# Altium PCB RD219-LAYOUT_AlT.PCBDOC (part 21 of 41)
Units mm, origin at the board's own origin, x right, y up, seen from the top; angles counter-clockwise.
Board outline 209.75 x 159.97 mm, 2 copper layers (TOP, BOTTOM), stack 0 mm thick; 398 components, 199 nets, 1469 pads, 0 vias.
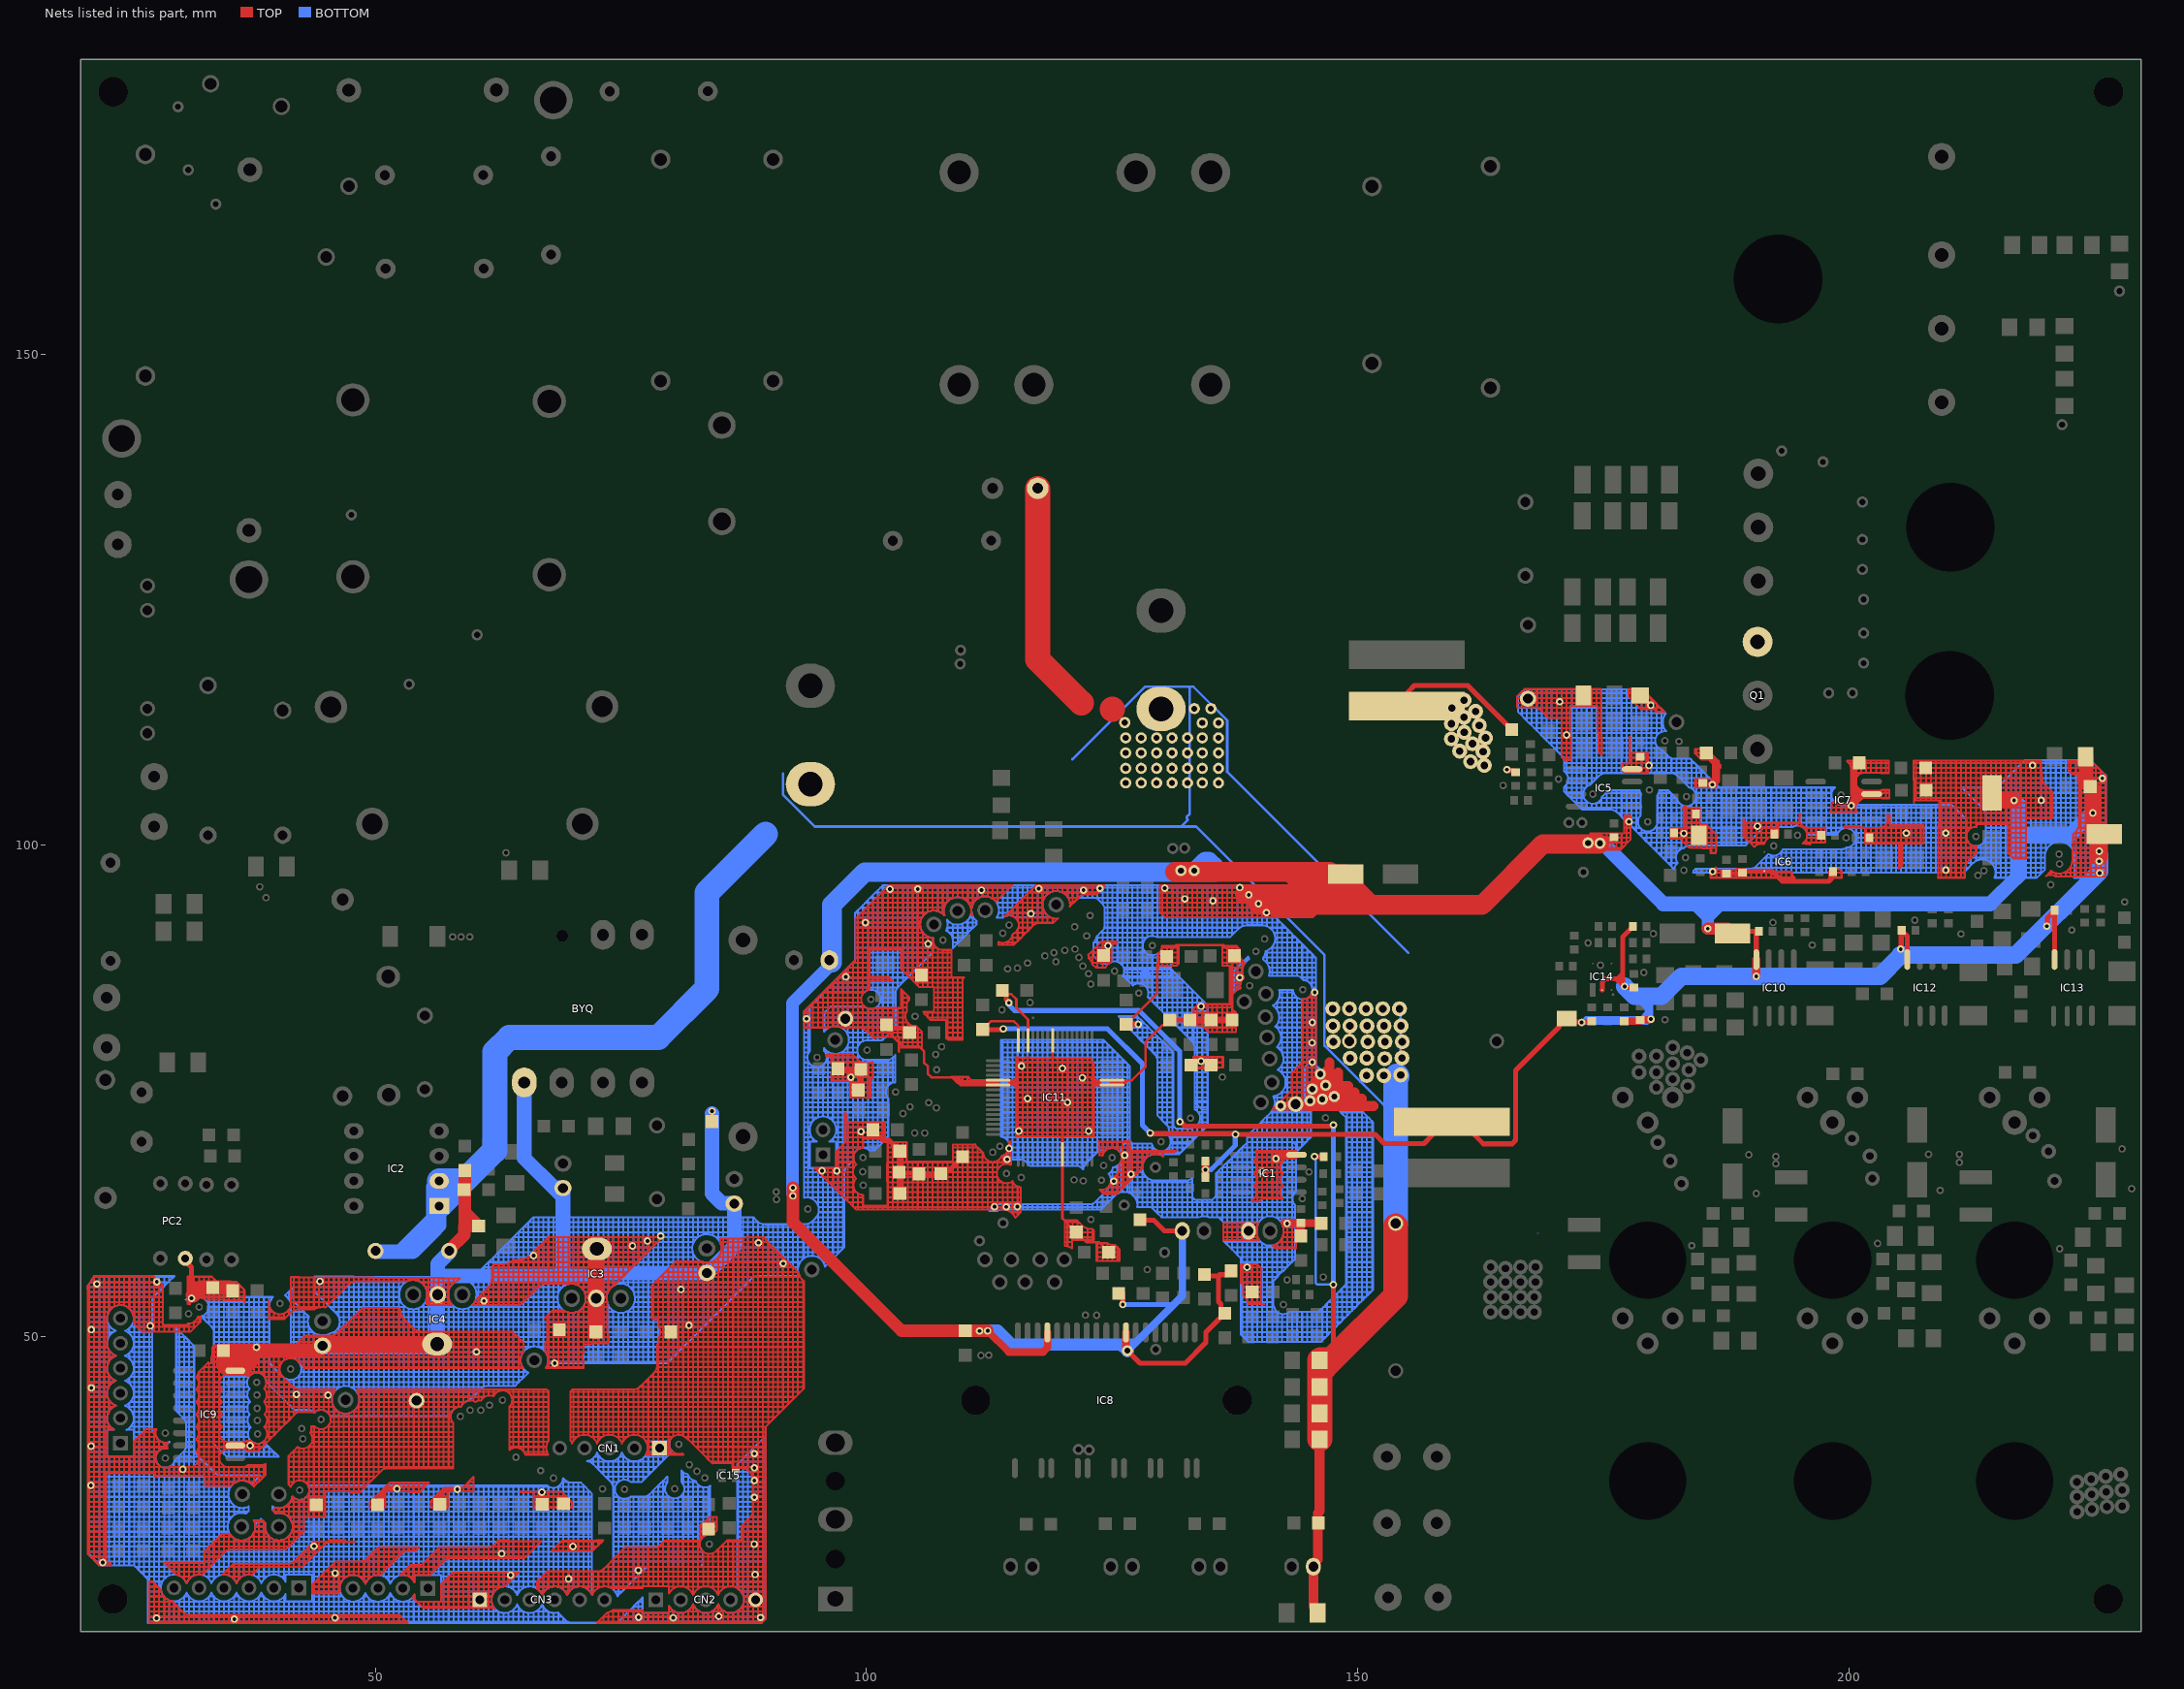
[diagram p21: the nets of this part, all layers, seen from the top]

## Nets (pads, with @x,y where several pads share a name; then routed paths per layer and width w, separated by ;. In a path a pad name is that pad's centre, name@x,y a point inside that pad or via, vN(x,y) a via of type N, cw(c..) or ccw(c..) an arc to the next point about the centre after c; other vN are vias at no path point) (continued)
GND: (continued)
  BOTTOM w0.203: 29.525,25.797 29.525,26.096 ; 29.525,26.096 29.525,26.604 ; 29.525,26.096 30.033,26.096 ; 29.525,26.604 30.033,26.604 ; 29.525,26.604 29.525,27.112 ; 29.525,27.112 29.525,27.62 ; 29.525,27.112 30.033,27.112 ; 29.525,27.62 29.525,28.128 ; 29.525,27.62 30.033,27.62 ; 29.525,28.128 29.525,28.636 ; 29.525,28.128 30.033,28.128 ; 29.525,28.636 29.525,29.144 ; 29.525,28.636 30.033,28.636 ; 29.525,29.144 29.525,29.652 ; 29.525,29.144 30.033,29.144 ; 29.525,29.652 29.525,30.16 ; 29.525,29.652 30.033,29.652 ; 29.525,30.16 29.525,30.668 ; 29.525,30.16 30.033,30.16 ; 29.525,30.668 29.525,31.176 ; 29.525,30.668 30.033,30.668 ; 29.525,31.176 29.525,31.684 ; 29.525,31.176 30.033,31.176 ; 29.525,31.684 29.525,32.192 ; 29.525,31.684 30.033,31.684 ; 29.525,32.192 29.525,32.7 ; 29.525,32.192 30.033,32.192 ; 29.525,32.7 29.525,33.208 ; 29.525,32.7 30.033,32.7 ; 29.525,33.208 29.525,33.716 ; 29.525,33.208 30.033,33.208 ; 29.525,33.716 29.525,34.224 ; 29.525,33.716 30.033,33.716 ; 29.525,34.224 29.525,34.732 ; 29.525,34.224 30.033,34.224 ; 29.525,34.732 29.525,35.24 ; 29.525,34.732 30.033,34.732 ; 29.525,35.24 29.525,35.748 ; 29.525,35.24 30.033,35.24 ; 29.525,35.748 29.525,36.256 ; 29.525,35.748 30.033,35.748 ; 29.525,36.256 30.033,36.256 ; 29.525,36.256 29.525,36.764 ; 29.525,36.764 30.033,36.764 ; 29.525,36.764 29.525,37.234 ; 29.525,37.234 ccw(c28.636,37.653) 29.542,37.272 ; 29.542,37.272 ccw(c28.636,37.653) 29.585,37.397 ; 29.542,37.272 30.033,37.272 ; 29.585,37.397 29.967,37.78 ; 29.742,42.86 30.033,42.86 ; 29.742,42.86 29.742,43.368 ; 29.742,42.86 29.742,42.451 29.84,42.352 ; 29.742,43.368 30.033,43.368 ; 29.742,43.368 29.742,43.876 ; 29.742,43.876 30.033,43.876 ; 29.742,43.876 29.742,44.384 ; 29.742,44.384 30.033,44.384 ; 29.742,44.384 29.742,44.892 ; 29.742,44.892 30.033,44.892 ; 29.742,44.892 29.742,45.4 ; 29.742,45.4 30.033,45.4 ; 29.742,45.4 29.742,45.908 ; 29.742,45.908 30.033,45.908 ; 29.742,45.908 29.742,46.416 ; 29.742,46.416 30.033,46.416 ; 29.742,46.416 29.742,46.924 ; 29.742,46.924 30.033,46.924 ; 29.742,46.924 29.742,47.432 ; 29.742,47.432 30.033,47.432 ; 29.742,47.432 29.742,47.94 ; 29.742,47.94 30.033,47.94 ; 29.742,47.94 29.742,48.448 ; 29.742,48.448 29.742,48.956 ; 29.742,48.448 30.033,48.448 ; 29.742,48.956 29.742,49.464 ; 29.742,48.956 30.033,48.956 ; 29.742,49.464 29.742,49.972 ; 29.742,49.464 30.033,49.464 ; 29.742,49.972 29.742,50.48 ; 29.742,49.972 30.033,49.972 ; 29.742,50.48 30.033,50.48 ; 29.742,50.48 29.742,50.884 30.033,50.593 ; 29.84,42.352 30.033,42.159 ; 29.84,42.352 30.033,42.352 ; 29.967,37.78 30.033,37.78 ; 29.967,37.78 30.033,37.846 ; 30.033,20.889 30.033,21.016 ; 30.033,20.889 30.541,20.889 ; 30.033,21.016 30.033,21.524 ; 30.033,21.016 30.541,21.016 ; 30.033,21.524 30.033,22.032 ; 30.033,21.524 30.541,21.524 ; 30.033,22.032 30.033,22.54 ; 30.033,22.032 30.541,22.032 ; 30.033,22.54 30.033,23.048 ; 30.033,22.54 30.541,22.54 ; 30.033,23.048 30.541,23.048 ; 30.033,23.048 30.033,23.192 ; 30.033,23.192 ccw(c29.525,24.445) 30.541,23.554 ; 30.033,25.698 30.033,26.096 ; 30.033,26.096 30.033,26.604 ; 30.033,26.096 30.541,26.096 ; 30.033,26.604 30.541,26.604 ; 30.033,26.604 30.033,27.112 ; 30.033,27.112 30.033,27.62 ; 30.033,27.112 30.541,27.112 ; 30.033,27.62 30.033,28.128 ; 30.033,27.62 30.541,27.62 ; 30.033,28.128 30.033,28.636 ; 30.033,28.128 30.541,28.128 ; 30.033,28.636 30.033,29.144 ; 30.033,28.636 30.541,28.636 ; 30.033,29.144 30.033,29.652 ; 30.033,29.144 30.541,29.144 ; 30.033,29.652 30.033,30.16 ; 30.033,29.652 30.541,29.652 ; 30.033,30.16 30.033,30.668 ; 30.033,30.16 30.541,30.16 ; 30.033,30.668 30.033,31.176 ; 30.033,30.668 30.541,30.668 ; 30.033,31.176 30.033,31.684 ; 30.033,31.176 30.541,31.176 ; 30.033,31.684 30.033,32.192 ; 30.033,31.684 30.541,31.684 ; 30.033,32.192 30.541,32.192 ; 30.033,32.192 30.033,32.7 ; 30.033,32.7 30.033,33.208 ; 30.033,32.7 30.541,32.7 ; 30.033,33.208 30.033,33.716 ; 30.033,33.208 30.541,33.208 ; 30.033,33.716 30.033,34.224 ; 30.033,33.716 30.541,33.716 ; 30.033,34.224 30.033,34.732 ; 30.033,34.224 30.541,34.224 ; 30.033,34.732 30.541,34.732 ; 30.033,34.732 30.033,35.24 ; 30.033,35.24 30.541,35.24 ; 30.033,35.24 30.033,35.748 ; 30.033,35.748 30.541,35.748 ; 30.033,35.748 30.033,36.256 ; 30.033,36.256 pad.@30.541,36.256 ; 30.033,36.256 30.033,36.764 ; 30.033,36.764 30.033,37.272 ; 30.033,36.764 pad.@30.541,36.764 ; 30.033,37.272 30.033,37.78 ; 30.033,37.272 30.541,37.272 ; 30.033,37.78 30.541,37.78 ; 30.033,37.78 30.033,37.846 ; 30.033,37.846 30.475,38.288 ; 30.033,42.159 30.348,41.844 ; 30.033,42.159 30.033,42.352 ; 30.033,42.352 30.541,42.352 ; 30.033,42.352 30.033,42.86 ; 30.033,42.86 30.033,43.368 ; 30.033,42.86 30.541,42.86 ; 30.033,43.368 30.033,43.876 ; 30.033,43.368 30.541,43.368 ; 30.033,43.876 30.033,44.384 ; 30.033,43.876 30.541,43.876 ; 30.033,44.384 30.033,44.892 ; 30.033,44.384 30.541,44.384 ; 30.033,44.892 30.033,45.4 ; 30.033,44.892 30.541,44.892 ; 30.033,45.4 30.033,45.908 ; 30.033,45.4 30.541,45.4 ; 30.033,45.908 30.033,46.416 ; 30.033,45.908 30.541,45.908 ; 30.033,46.416 30.033,46.924 ; 30.033,46.416 30.541,46.416 ; 30.033,46.924 30.033,47.432 ; 30.033,46.924 30.541,46.924 ; 30.033,47.432 30.033,47.94 ; 30.033,47.432 30.541,47.432 ; 30.033,47.94 30.033,48.448 ; 30.033,47.94 30.541,47.94 ; 30.033,48.448 30.033,48.956 ; 30.033,48.448 30.541,48.448 ; 30.033,48.956 30.541,48.956 ; 30.033,48.956 30.033,49.464 ; 30.033,49.464 30.033,49.972 ; 30.033,49.464 30.541,49.464 ; 30.033,49.972 30.541,49.972 ; 30.033,49.972 30.033,50.48 ; 30.033,50.48 30.033,50.593 ; 30.033,50.48 30.146,50.48 ; 30.033,50.593 30.146,50.48 ; 30.146,50.48 30.541,50.085 ; 30.348,41.844 30.541,41.844 ; 30.475,38.288 30.541,38.288 ; 30.541,20.889 30.541,21.016 ; 30.541,20.889 31.049,20.889 ; 30.541,21.016 30.541,21.524 ; 30.541,21.016 31.049,21.016 ; 30.541,21.524 30.541,22.032 ; 30.541,21.524 31.049,21.524 ; 30.541,22.032 30.541,22.54 ; 30.541,22.032 31.049,22.032 ; 30.541,22.54 30.541,23.048 ; 30.541,22.54 31.049,22.54 ; 30.541,23.048 31.049,23.048 ; 30.541,23.048 30.541,23.554 ; 30.541,23.554 ccw(c29.525,24.445) 30.543,23.556 ; 30.541,25.336 cw(c29.525,24.445) 30.545,25.332 cw(c29.525,24.445) 30.718,25.08 ; 30.541,25.336 30.541,25.588 ; 30.541,25.588 30.541,26.096 ; 30.541,25.588 31.049,25.588 ; 30.541,26.096 30.541,26.604 ; 30.541,26.096 31.049,26.096 ; 30.541,26.604 31.049,26.604 ; 30.541,26.604 30.541,27.112 ; 30.541,27.112 30.541,27.62 ; 30.541,27.112 31.049,27.112 ; 30.541,27.62 30.541,28.128 ; 30.541,27.62 31.049,27.62 ; 30.541,28.128 30.541,28.636 ; 30.541,28.128 31.049,28.128 ; 30.541,28.636 30.541,29.144 ; 30.541,28.636 31.049,28.636 ; 30.541,29.144 30.541,29.652 ; 30.541,29.144 31.049,29.144 ; 30.541,29.652 30.541,30.16 ; 30.541,29.652 31.049,29.652 ; 30.541,30.16 30.541,30.668 ; 30.541,30.16 31.049,30.16 ; 30.541,30.668 30.541,31.176 ; 30.541,30.668 31.049,30.668 ; 30.541,31.176 30.541,31.684 ; 30.541,31.176 31.049,31.176 ; 30.541,31.684 30.541,32.192 ; 30.541,31.684 31.049,31.684 ; 30.541,32.192 30.541,32.7 ; 30.541,32.192 31.049,32.192 ; 30.541,32.7 30.541,33.208 ; 30.541,32.7 31.049,32.7 ; 30.541,33.208 30.541,33.716 ; 30.541,33.208 31.049,33.208 ; 30.541,33.716 30.541,34.224 ; 30.541,33.716 31.049,33.716 ; 30.541,34.224 30.541,34.732 ; 30.541,34.224 31.049,34.224 ; 30.541,34.732 31.049,34.732 ; 30.541,34.732 30.541,35.24 ; 30.541,35.24 31.049,35.24 ; 30.541,35.24 30.541,35.748 ; 30.541,35.748 31.049,35.748 ; 30.541,35.748 pad.@30.541,36.256 ; pad.@30.541,36.256 31.049,36.256 ; pad.@30.541,36.256 pad.@30.541,36.764 ; pad.@30.541,36.764 30.541,37.272 ; pad.@30.541,36.764 31.049,36.764 ; 30.541,37.272 31.049,37.272 ; 30.541,37.272 30.541,37.78 ; 30.541,37.78 30.541,38.288 ; 30.541,37.78 31.049,37.78 ; 30.541,38.288 31.049,38.288 ; 30.541,38.288 30.541,38.356 ; 30.541,38.356 cw(c29.906,38.923) 30.508,38.321 ccw(c29.906,38.923) 30.541,38.356 ; 30.541,38.356 ccw(c29.906,38.923) 30.748,38.796 ; 30.541,38.356 ccw(c29.906,38.923) 30.748,38.796 ; 30.541,41.649 cw(c29.906,41.082) 30.719,41.336 ; 30.541,41.649 cw(c29.906,41.082) 30.719,41.336 ; 30.541,41.649 ccw(c29.906,41.082) 30.508,41.684 cw(c29.906,41.082) 30.541,41.649 ; 30.541,41.649 30.541,41.844 ; 30.541,41.844 31.049,41.844 ; 30.541,41.844 30.541,42.352 ; 30.541,42.352 31.049,42.352 ; 30.541,42.352 30.541,42.86 ; 30.541,42.86 30.541,43.368 ; 30.541,42.86 31.049,42.86 ; 30.541,43.368 30.541,43.876 ; 30.541,43.368 31.049,43.368 ; 30.541,43.876 30.541,44.384 ; 30.541,43.876 31.049,43.876 ; 30.541,44.384 30.541,44.892 ; 30.541,44.384 31.049,44.384 ; 30.541,44.892 30.541,45.4 ; 30.541,44.892 31.049,44.892 ; 30.541,45.4 30.541,45.908 ; 30.541,45.4 31.049,45.4 ; 30.541,45.908 30.541,46.416 ; 30.541,45.908 31.049,45.908 ; 30.541,46.416 30.541,46.924 ; 30.541,46.416 31.049,46.416 ; 30.541,46.924 30.541,47.432 ; 30.541,46.924 31.049,46.924 ; 30.541,47.432 30.541,47.94 ; 30.541,47.432 31.049,47.432 ; 30.541,47.94 30.541,48.448 ; 30.541,47.94 31.049,47.94 ; 30.541,48.448 30.541,48.956 ; 30.541,48.448 31.049,48.448 ; 30.541,48.956 31.049,48.956 ; 30.541,48.956 30.541,49.464 ; 30.541,49.464 31.049,49.464 ; 30.541,49.464 30.541,49.972 ; 30.541,49.972 30.654,49.972 ; 30.541,49.972 30.541,50.085 ; 30.541,50.085 30.654,49.972 ; 30.543,23.556 ccw(c29.525,24.445) 30.545,23.558 ccw(c29.525,24.445) 30.795,23.982 ccw(c32.065,24.445) 31.045,23.558 ccw(c32.065,24.445) 31.047,23.556 ; 30.543,23.556 31.047,23.556 ; 30.654,49.972 31.049,49.577 ; 30.718,25.08 cw(c29.525,24.445) 30.795,24.908 cw(c32.065,24.445) 30.872,25.08 ; 30.718,25.08 30.872,25.08 ; 30.719,41.336 cw(c29.906,41.082) 30.72,41.331 ; 30.719,41.336 cw(c29.906,41.082) 30.72,41.331 ; 30.719,41.336 31.049,41.336 ; 30.72,41.331 cw(c29.906,41.082) 30.758,41.082 ; 30.72,41.331 cw(c29.906,41.082) 30.758,41.082 ; 30.748,38.796 ccw(c29.906,38.923) 30.758,38.923 ; 30.748,38.796 ccw(c29.906,38.923) 30.758,38.923 ; 30.748,38.796 31.049,38.796 ; 30.758,38.923 30.758,39.304 ; 30.758,39.304 31.049,39.304 ; 30.758,39.304 30.758,39.812 ; 30.758,39.812 31.049,39.812 ; 30.758,39.812 30.758,40.32 ; 30.758,40.32 31.049,40.32 ; 30.758,40.32 30.758,40.828 ; 30.758,40.828 31.049,40.828 ; 30.758,40.828 30.758,41.082 ; pad.@30.983,54.036 pad.@31.049,54.036 ; pad.@30.983,54.036 31.021,54.073 pad.@31.049,54.073 ; 31.047,23.556 ccw(c32.065,24.445) 31.049,23.554 ; 31.049,20.889 31.049,21.016 ; 31.049,20.889 31.557,20.889 ; 31.049,21.016 31.049,21.524 ; 31.049,21.016 31.557,21.016 ; 31.049,21.524 31.049,22.032 ; 31.049,21.524 31.557,21.524 ; 31.049,22.032 31.049,22.54 ; 31.049,22.032 31.557,22.032 ; 31.049,22.54 31.049,23.048 ; 31.049,22.54 31.557,22.54 ; 31.049,23.048 31.557,23.048 ; 31.049,23.048 31.049,23.554 ; 31.049,23.554 ccw(c32.065,24.445) 31.557,23.193 ; 31.049,25.588 31.049,26.096 ; 31.049,25.588 31.344,25.588 ; 31.049,26.096 31.049,26.604 ; 31.049,26.096 31.557,26.096 ; 31.049,26.604 31.557,26.604 ; 31.049,26.604 31.049,27.112 ; 31.049,27.112 31.049,27.62 ; 31.049,27.112 31.557,27.112 ; 31.049,27.62 31.049,28.128 ; 31.049,27.62 31.557,27.62 ; 31.049,28.128 31.049,28.636 ; 31.049,28.128 31.557,28.128 ; 31.049,28.636 31.049,29.144 ; 31.049,28.636 31.557,28.636 ; 31.049,29.144 31.049,29.652 ; 31.049,29.144 31.557,29.144 ; 31.049,29.652 31.049,30.16 ; 31.049,29.652 31.557,29.652 ; 31.049,30.16 31.049,30.668 ; 31.049,30.16 31.557,30.16 ; 31.049,30.668 31.049,31.176 ; 31.049,30.668 31.557,30.668 ; 31.049,31.176 31.049,31.684 ; 31.049,31.176 31.557,31.176 ; 31.049,31.684 31.049,32.192 ; 31.049,31.684 31.557,31.684 ; 31.049,32.192 31.557,32.192 ; 31.049,32.192 31.049,32.7 ; 31.049,32.7 31.049,33.208 ; 31.049,32.7 31.557,32.7 ; 31.049,33.208 31.049,33.716 ; 31.049,33.208 31.557,33.208 ; 31.049,33.716 31.049,34.224 ; 31.049,33.716 31.557,33.716 ; 31.049,34.224 31.049,34.732 ; 31.049,34.224 31.557,34.224 ; 31.049,34.732 31.557,34.732 ; 31.049,34.732 31.049,35.24 ; 31.049,35.24 31.557,35.24 ; 31.049,35.24 31.049,35.748 ; 31.049,35.748 31.557,35.748 ; 31.049,35.748 31.049,36.256 ; 31.049,36.256 31.557,36.256 ; 31.049,36.256 31.049,36.764 ; 31.049,36.764 31.049,37.272 ; 31.049,36.764 31.557,36.764 ; 31.049,37.272 31.557,37.272 ; 31.049,37.272 31.049,37.78 ; 31.049,37.78 31.049,38.288 ; 31.049,37.78 31.557,37.78 ; 31.049,38.288 31.557,38.288 ; 31.049,38.288 31.049,38.796 ; 31.049,38.796 31.557,38.796 ; 31.049,38.796 31.049,39.304 ; 31.049,39.304 31.049,39.812 ; 31.049,39.304 31.557,39.304 ; 31.049,39.812 31.049,40.32 ; 31.049,39.812 31.557,39.812 ; 31.049,40.32 31.049,40.828 ; 31.049,40.32 31.557,40.32 ; 31.049,40.828 31.049,41.336 ; 31.049,40.828 31.557,40.828 ; 31.049,41.336 31.049,41.844 ; 31.049,41.336 31.557,41.336 ; 31.049,41.844 31.049,42.352 ; 31.049,41.844 31.557,41.844 ; 31.049,42.352 31.557,42.352 ; 31.049,42.352 31.049,42.86 ; 31.049,42.86 31.049,43.368 ; 31.049,42.86 31.557,42.86 ; 31.049,43.368 31.049,43.876 ; 31.049,43.368 31.557,43.368 ; 31.049,43.876 31.049,44.384 ; 31.049,43.876 31.557,43.876 ; 31.049,44.384 31.049,44.892 ; 31.049,44.384 31.557,44.384 ; 31.049,44.892 31.049,45.4 ; 31.049,44.892 31.557,44.892 ; 31.049,45.4 31.049,45.908 ; 31.049,45.4 31.557,45.4 ; 31.049,45.908 31.049,46.416 ; 31.049,45.908 31.557,45.908 ; 31.049,46.416 31.049,46.924 ; 31.049,46.416 31.557,46.416 ; 31.049,46.924 31.049,47.432 ; 31.049,46.924 31.557,46.924 ; 31.049,47.432 31.049,47.94 ; 31.049,47.432 31.557,47.432 ; 31.049,47.94 31.049,48.448 ; 31.049,47.94 31.557,47.94 ; 31.049,48.448 31.049,48.956 ; 31.049,48.448 31.557,48.448 ; 31.049,48.956 31.049,49.464 ; 31.049,48.956 31.557,48.956 ; 31.049,49.464 31.162,49.464 ; 31.049,49.464 31.049,49.577 ; 31.049,49.577 31.162,49.464 ; pad.@31.049,53.754 pad.@31.049,54.036 ; pad.@31.049,54.036 pad.@31.049,54.073 ; pad.@31.049,54.036 pad.@31.557,54.036 ; pad.@31.049,54.073 pad.@31.557,54.073 ; 31.162,49.464 31.557,49.069 ; 31.344,25.588 cw(c32.065,24.445) 31.349,25.591 cw(c32.065,24.445) 31.557,25.697 ; 31.557,20.889 31.557,21.016 ; 31.557,20.889 32.065,20.889 ; 31.557,21.016 31.557,21.524 ; 31.557,21.016 32.065,21.016 ; 31.557,21.524 31.557,22.032 ; 31.557,21.524 32.065,21.524 ; 31.557,22.032 31.557,22.54 ; 31.557,22.032 32.065,22.032 ; 31.557,22.54 31.557,23.048 ; 31.557,22.54 32.065,22.54 ; 31.557,23.048 32.065,23.048 ; 31.557,23.048 31.557,23.193 ; 31.557,23.193 ccw(c32.065,24.445) 31.559,23.192 ccw(c32.065,24.445) 32.065,23.093 ; 31.557,25.697 cw(c32.065,24.445) 31.559,25.698 cw(c32.065,24.445) 32.065,25.797 ; 31.557,25.698 31.557,26.096 ; 31.557,26.096 31.557,26.604 ; 31.557,26.096 32.065,26.096 ; 31.557,26.604 32.065,26.604 ; 31.557,26.604 31.557,27.112 ; 31.557,27.112 31.557,27.62 ; 31.557,27.112 32.065,27.112 ; 31.557,27.62 31.557,28.128 ; 31.557,27.62 32.065,27.62 ; 31.557,28.128 31.557,28.636 ; 31.557,28.128 32.065,28.128 ; 31.557,28.636 31.557,29.144 ; 31.557,28.636 32.065,28.636 ; 31.557,29.144 31.557,29.652 ; 31.557,29.144 32.065,29.144 ; 31.557,29.652 31.557,30.16 ; 31.557,29.652 32.065,29.652 ; 31.557,30.16 31.557,30.668 ; 31.557,30.16 32.065,30.16 ; 31.557,30.668 31.557,31.176 ; 31.557,30.668 32.065,30.668 ; 31.557,31.176 31.557,31.684 ; 31.557,31.176 32.065,31.176 ; 31.557,31.684 31.557,32.192 ; 31.557,31.684 32.065,31.684 ; 31.557,32.192 32.065,32.192 ; 31.557,32.192 31.557,32.7 ; 31.557,32.7 31.557,33.208 ; 31.557,32.7 32.065,32.7 ; 31.557,33.208 31.557,33.716 ; 31.557,33.208 32.065,33.208 ; 31.557,33.716 31.557,34.224 ; 31.557,33.716 32.065,33.716 ; 31.557,34.224 31.557,34.732 ; 31.557,34.224 32.065,34.224 ; 31.557,34.732 32.065,34.732 ; 31.557,34.732 31.557,35.24 ; 31.557,35.24 32.065,35.24 ; 31.557,35.24 31.557,35.748 ; 31.557,35.748 32.065,35.748 ; 31.557,35.748 31.557,36.256 ; 31.557,36.256 32.065,36.256 ; 31.557,36.256 31.557,36.764 ; 31.557,36.764 31.557,37.272 ; 31.557,36.764 32.065,36.764 ; 31.557,37.272 32.065,37.272 ; 31.557,37.272 31.557,37.78 ; 31.557,37.78 31.557,38.288 ; 31.557,37.78 32.051,37.78 ; 31.557,38.288 31.557,38.796 ; 31.557,38.288 31.636,38.288 ; 31.557,38.796 31.557,39.304 ; 31.557,38.796 31.59,38.796 ; 31.557,39.304 31.557,39.812 ; 31.557,39.304 31.59,39.304 ; 31.557,39.812 31.557,40.32 ; 31.557,39.812 31.59,39.812 ; 31.557,40.32 31.557,40.828 ; 31.557,40.32 31.59,40.32 ; 31.557,40.828 31.557,41.336 ; 31.557,40.828 31.59,40.828 ; 31.557,41.336 31.557,41.844 ; 31.557,41.336 31.59,41.336 ; 31.557,41.844 31.557,42.352 ; 31.557,41.844 31.59,41.844 ; 31.557,42.352 31.59,42.352 ; 31.557,42.352 31.557,42.86 ; 31.557,42.86 31.557,43.368 ; 31.557,42.86 31.59,42.86 ; 31.557,43.368 31.557,43.876 ; 31.557,43.368 31.59,43.368 ; 31.557,43.876 31.557,44.384 ; 31.557,43.876 31.59,43.876 ; 31.557,44.384 31.557,44.892 ; 31.557,44.384 31.59,44.384 ; 31.557,44.892 31.557,45.4 ; 31.557,44.892 31.59,44.892 ; 31.557,45.4 31.557,45.908 ; 31.557,45.4 31.59,45.4 ; 31.557,45.908 31.557,46.416 ; 31.557,45.908 31.59,45.908 ; 31.557,46.416 31.557,46.924 ; 31.557,46.416 31.59,46.416 ; 31.557,46.924 31.557,47.432 ; 31.557,46.924 31.59,46.924 ; 31.557,47.432 31.557,47.94 ; 31.557,47.432 31.59,47.432 ; 31.557,47.94 31.557,48.448 ; 31.557,47.94 31.59,47.94 ; 31.557,48.448 31.557,48.956 ; 31.557,48.448 31.59,48.448 ; 31.557,48.956 31.557,49.069 ; 31.557,48.956 31.59,48.956 ; 31.557,49.069 31.59,49.035 31.59,48.956 ; pad.@31.557,53.863 cw(c32.071,53.026) 32.573,53.87 ; pad.@31.557,53.863 pad.@31.557,54.036 ; pad.@31.557,54.036 32.573,54.036 ; pad.@31.557,54.036 pad.@31.557,54.073 ; pad.@31.557,54.073 32.573,54.073 ; 31.59,38.542 ccw(c32.319,38.542) 31.636,38.288 ; 31.59,38.542 ccw(c32.319,38.542) 31.636,38.288 ; 31.59,38.542 31.59,38.796 ; 31.59,38.796 31.59,39.304 ; 31.59,39.304 31.59,39.812 ; 31.59,39.812 31.59,40.32 ; 31.59,40.32 31.59,40.828 ; 31.59,40.828 31.59,41.336 ; 31.59,41.336 31.59,41.844 ; 31.59,41.844 31.59,42.352 ; 31.59,42.352 31.59,42.86 ; 31.59,42.86 31.59,43.368 ; 31.59,43.368 31.59,43.876 ; 31.59,43.876 31.59,44.384 ; 31.59,44.384 31.59,44.892 ; 31.59,44.892 31.59,45.4 ; 31.59,45.4 31.59,45.908 ; 31.59,45.908 31.59,46.416 ; 31.59,46.416 31.59,46.924 ; 31.59,46.924 31.59,47.432 ; 31.59,47.432 31.59,47.94 ; 31.59,47.94 31.59,48.448 ; 31.59,48.448 31.59,48.956 ; 31.636,38.288 ccw(c32.319,38.542) 31.804,38.027 ; 31.636,38.288 ccw(c32.319,38.542) 31.804,38.027 ; 31.804,38.027 32.051,37.78 ; 32.051,37.78 32.065,37.766 ; 32.065,20.889 32.065,21.016 ; 32.065,20.889 32.573,20.889 ; 32.065,21.016 32.065,21.524 ; 32.065,21.016 32.573,21.016 ; 32.065,21.524 32.065,22.032 ; 32.065,21.524 32.573,21.524 ; 32.065,22.032 32.065,22.54 ; 32.065,22.032 32.573,22.032 ; 32.065,22.54 32.065,23.048 ; 32.065,22.54 32.573,22.54 ; 32.065,23.048 32.573,23.048 ; 32.065,23.048 32.065,23.093 ; 32.065,23.093 ccw(c32.065,24.445) 32.571,23.192 ccw(c32.065,24.445) 32.573,23.192 ; 32.065,25.797 cw(c32.065,24.445) 32.571,25.698 cw(c32.065,24.445) 32.573,25.698 ; 32.065,25.797 32.065,26.096 ; 32.065,26.096 32.065,26.604 ; 32.065,26.096 32.573,26.096 ; 32.065,26.604 32.573,26.604 ; 32.065,26.604 32.065,27.112 ; 32.065,27.112 32.065,27.62 ; 32.065,27.112 32.573,27.112 ; 32.065,27.62 32.065,28.128 ; 32.065,27.62 32.573,27.62 ; 32.065,28.128 32.065,28.636 ; 32.065,28.128 32.573,28.128 ; 32.065,28.636 32.065,29.144 ; 32.065,28.636 32.573,28.636 ; 32.065,29.144 32.065,29.652 ; 32.065,29.144 32.573,29.144 ; 32.065,29.652 32.065,30.16 ; 32.065,29.652 32.573,29.652 ; 32.065,30.16 32.065,30.668 ; 32.065,30.16 32.573,30.16 ; 32.065,30.668 32.065,31.176 ; 32.065,30.668 32.573,30.668 ; 32.065,31.176 32.065,31.684 ; 32.065,31.176 32.573,31.176 ; 32.065,31.684 32.065,32.192 ; 32.065,31.684 32.573,31.684 ; 32.065,32.192 32.573,32.192 ; 32.065,32.192 32.065,32.7 ; 32.065,32.7 32.065,33.208 ; 32.065,32.7 32.573,32.7 ; 32.065,33.208 32.065,33.716 ; 32.065,33.208 32.573,33.208 ; 32.065,33.716 32.065,34.224 ; 32.065,33.716 32.573,33.716 ; 32.065,34.224 32.065,34.732 ; 32.065,34.224 32.573,34.224 ; 32.065,34.732 32.573,34.732 ; 32.065,34.732 32.065,35.24 ; 32.065,35.24 32.573,35.24 ; 32.065,35.24 32.065,35.748 ; 32.065,35.748 32.573,35.748 ; 32.065,35.748 32.065,36.256 ; 32.065,36.256 32.573,36.256 ; 32.065,36.256 32.065,36.764 ; 32.065,36.764 32.065,37.272 ; 32.065,36.764 32.573,36.764 ; 32.065,37.272 32.065,37.766 ; 32.065,37.272 32.559,37.272 ; 32.065,37.766 32.559,37.272 ; 32.358,52.004 32.573,51.789 ; 32.358,52.004 32.573,52.004 ; 32.358,52.004 32.293,52.068 ccw(c32.071,53.026) 32.573,52.181 ; 32.559,37.272 32.573,37.258 ; 32.573,20.889 32.573,21.016 ; 32.573,20.889 33.081,20.889 ; 32.573,21.016 32.573,21.524 ; 32.573,21.016 33.081,21.016 ; 32.573,21.524 32.573,22.032 ; 32.573,21.524 33.081,21.524 ; 32.573,22.032 32.573,22.54 ; 32.573,22.032 33.081,22.032 ; 32.573,22.54 32.573,23.048 ; 32.573,22.54 33.081,22.54 ; 32.573,23.048 33.081,23.048 ; 32.573,23.048 32.573,23.192 ; 32.573,23.192 ccw(c32.065,24.445) 33.081,23.554 ; 32.573,25.698 32.573,26.096 ; 32.573,26.096 32.573,26.604 ; 32.573,26.096 33.081,26.096 ; 32.573,26.604 32.573,27.112 ; 32.573,26.604 33.081,26.604 ; 32.573,27.112 32.573,27.62 ; 32.573,27.112 33.081,27.112 ; 32.573,27.62 32.573,28.128 ; 32.573,27.62 33.081,27.62 ; 32.573,28.128 32.573,28.636 ; 32.573,28.128 33.081,28.128 ; 32.573,28.636 32.573,29.144 ; 32.573,28.636 33.081,28.636 ; 32.573,29.144 32.573,29.652 ; 32.573,29.144 33.081,29.144 ; 32.573,29.652 32.573,30.16 ; 32.573,29.652 33.081,29.652 ; 32.573,30.16 32.573,30.668 ; 32.573,30.16 33.081,30.16 ; 32.573,30.668 32.573,31.176 ; 32.573,30.668 33.081,30.668 ; 32.573,31.176 32.573,31.684 ; 32.573,31.176 33.081,31.176 ; 32.573,31.684 32.573,32.192 ; 32.573,31.684 33.081,31.684 ; 32.573,32.192 32.573,32.7 ; 32.573,32.192 33.081,32.192 ; 32.573,32.7 32.573,33.208 ; 32.573,32.7 33.081,32.7 ; 32.573,33.208 32.573,33.716 ; 32.573,33.208 33.081,33.208 ; 32.573,33.716 32.573,34.224 ; 32.573,33.716 33.081,33.716 ; 32.573,34.224 32.573,34.732 ; 32.573,34.224 33.081,34.224 ; 32.573,34.732 33.081,34.732 ; 32.573,34.732 32.573,35.24 ; 32.573,35.24 33.081,35.24 ; 32.573,35.24 32.573,35.748 ; 32.573,35.748 33.081,35.748 ; 32.573,35.748 32.573,36.256 ; 32.573,36.256 33.081,36.256 ; 32.573,36.256 32.573,36.764 ; 32.573,36.764 33.067,36.764 ; 32.573,36.764 32.573,37.258 ; 32.573,37.258 33.067,36.764 ; 32.573,51.789 32.573,52.004 ; 32.573,51.789 32.866,51.496 ; 32.573,52.004 33.081,52.004 ; 32.573,52.004 32.573,52.181 ; 32.573,52.181 ccw(c32.071,53.026) 32.577,52.183 ccw(c32.071,53.026) 32.909,52.512 ; 32.573,53.87 cw(c32.071,53.026) 32.577,53.868 cw(c32.071,53.026) 32.916,53.528 ; 32.573,53.87 32.573,54.036 ; 32.573,54.036 32.573,54.073 ; 32.573,54.036 33.081,54.036 ; 32.573,54.073 33.081,54.073 ; 32.866,51.496 33.081,51.496 ; 32.866,51.496 33.081,51.281 ; 32.909,52.512 ccw(c32.071,53.026) 33.054,53.02 ; 32.909,52.512 33.081,52.512 ; 32.916,53.528 cw(c32.071,53.026) 33.054,53.026 cw(c32.071,53.026) 33.054,53.02 ; 32.916,53.528 33.081,53.528 ; 33.054,53.02 33.081,53.02 ; 33.067,36.764 33.081,36.75 ; 33.081,20.889 33.081,21.016 ; 33.081,20.889 33.589,20.889 ; 33.081,21.016 33.081,21.524 ; 33.081,21.016 33.589,21.016 ; 33.081,21.524 33.081,22.032 ; 33.081,21.524 33.589,21.524 ; 33.081,22.032 33.081,22.54 ; 33.081,22.032 33.589,22.032 ; 33.081,22.54 33.081,23.048 ; 33.081,22.54 33.589,22.54 ; 33.081,23.048 33.589,23.048 ; 33.081,23.048 33.081,23.554 ; 33.081,23.554 ccw(c32.065,24.445) 33.083,23.556 ; 33.081,25.336 cw(c32.065,24.445) 33.085,25.332 cw(c32.065,24.445) 33.258,25.08 ; 33.081,25.336 33.081,25.588 ; 33.081,25.588 33.081,26.096 ; 33.081,25.588 33.589,25.588 ; 33.081,26.096 33.081,26.604 ; 33.081,26.096 33.589,26.096 ; 33.081,26.604 33.589,26.604 ; 33.081,26.604 33.081,27.112 ; 33.081,27.112 33.081,27.62 ; 33.081,27.112 33.589,27.112 ; 33.081,27.62 33.081,28.128 ; 33.081,27.62 33.589,27.62 ; 33.081,28.128 33.081,28.636 ; 33.081,28.128 33.589,28.128 ; 33.081,28.636 33.081,29.144 ; 33.081,28.636 33.589,28.636 ; 33.081,29.144 33.081,29.652 ; 33.081,29.144 33.589,29.144 ; 33.081,29.652 33.081,30.16 ; 33.081,29.652 33.589,29.652 ; 33.081,30.16 33.081,30.668 ; 33.081,30.16 33.589,30.16 ; 33.081,30.668 33.081,31.176 ; 33.081,30.668 33.589,30.668 ; 33.081,31.176 33.081,31.684 ; 33.081,31.176 33.589,31.176 ; 33.081,31.684 33.081,32.192 ; 33.081,31.684 33.589,31.684 ; 33.081,32.192 33.589,32.192 ; 33.081,32.192 33.081,32.7 ; 33.081,32.7 33.081,33.208 ; 33.081,32.7 33.589,32.7 ; 33.081,33.208 33.081,33.716 ; 33.081,33.208 33.589,33.208 ; 33.081,33.716 33.081,34.224 ; 33.081,33.716 33.589,33.716 ; 33.081,34.224 33.081,34.732 ; 33.081,34.224 33.589,34.224 ; 33.081,34.732 33.589,34.732 ; 33.081,34.732 33.081,35.24 ; 33.081,35.24 33.589,35.24 ; 33.081,35.24 33.081,35.748 ; 33.081,35.748 33.589,35.748 ; 33.081,35.748 33.081,36.256 ; 33.081,36.256 33.575,36.256 ; 33.081,36.256 33.081,36.75 ; 33.081,36.75 33.575,36.256 ; 33.081,51.281 33.081,51.496 ; 33.081,51.281 33.342,51.02 ; 33.081,51.496 33.081,52.004 ; 33.081,51.496 33.589,51.496 ; 33.081,52.004 33.589,52.004 ; 33.081,52.004 33.081,52.512 ; 33.081,52.512 33.081,53.02 ; 33.081,52.512 33.589,52.512 ; 33.081,53.02 33.589,53.02 ; 33.081,53.02 33.081,53.528 ; 33.081,53.528 33.589,53.528 ; 33.081,53.528 33.081,54.036 ; 33.081,54.036 33.589,54.036 ; 33.081,54.036 33.081,54.073 ; 33.081,54.073 33.589,54.073 ; 33.083,23.556 ccw(c32.065,24.445) 33.085,23.558 ccw(c32.065,24.445) 33.335,23.982 ccw(c34.605,24.445) 33.585,23.558 ccw(c34.605,24.445) 33.587,23.556 ; 33.083,23.556 33.587,23.556 ; 33.258,25.08 cw(c32.065,24.445) 33.335,24.908 cw(c34.605,24.445) 33.412,25.08 ; 33.258,25.08 33.412,25.08 ; 33.342,51.02 cw(c32.827,50.504) 33.372,50.988 ; 33.342,51.02 cw(c32.827,50.504) 33.372,50.988 ; 33.372,50.988 cw(c32.827,50.504) 33.556,50.504 ; 33.372,50.988 cw(c32.827,50.504) 33.556,50.504 ; 33.372,50.988 33.589,50.988 ; 33.556,39.304 33.589,39.304 ; 33.556,39.304 33.556,39.812 ; 33.556,39.304 33.556,39.098 33.589,39.064 ; 33.556,39.812 33.589,39.812 ; 33.556,39.812 33.556,40.32 ; 33.556,40.32 33.556,40.828 ; 33.556,40.32 33.589,40.32 ; 33.556,40.828 33.589,40.828 ; 33.556,40.828 33.556,41.336 ; 33.556,41.336 33.556,41.844 ; 33.556,41.336 33.589,41.336 ; 33.556,41.844 33.589,41.844 ; 33.556,41.844 33.556,42.352 ; 33.556,42.352 33.589,42.352 ; 33.556,42.352 33.556,42.86 ; 33.556,42.86 33.556,43.368 ; 33.556,42.86 33.589,42.86 ; 33.556,43.368 33.589,43.368 ; 33.556,43.368 33.556,43.876 ; 33.556,43.876 33.589,43.876 ; 33.556,43.876 33.556,44.384 ; 33.556,44.384 33.556,44.892 ; 33.556,44.384 33.589,44.384 ; 33.556,44.892 33.589,44.892 ; 33.556,44.892 33.556,45.4 ; 33.556,45.4 33.589,45.4 ; 33.556,45.4 33.556,45.908 ; 33.556,45.908 33.589,45.908 ; 33.556,45.908 33.556,46.416 ; 33.556,46.416 33.556,46.924 ; 33.556,46.416 33.589,46.416 ; 33.556,46.924 33.556,47.432 ; 33.556,46.924 33.589,46.924 ; 33.556,47.432 33.556,47.94 ; 33.556,47.432 33.589,47.432 ; 33.556,47.94 33.589,47.94 ; 33.556,47.94 33.556,48.448 ; 33.556,48.448 33.589,48.448 ; 33.556,48.448 33.556,48.956 ; 33.556,48.956 33.589,48.956 ; 33.556,48.956 33.556,49.464 ; 33.556,49.464 33.589,49.464 ; 33.556,49.464 33.556,49.972 ; 33.556,49.972 33.556,50.48 ; 33.556,49.972 33.589,49.972 ; 33.556,50.48 33.589,50.48 ; 33.556,50.48 33.556,50.504 ; 33.575,36.256 33.589,36.242 ; 33.587,23.556 ccw(c34.605,24.445) 33.589,23.554 ; 33.589,20.889 33.589,21.016 ; 33.589,20.889 34.097,20.889 ; 33.589,21.016 33.589,21.524 ; 33.589,21.016 34.097,21.016 ; 33.589,21.524 33.589,22.032 ; 33.589,21.524 34.097,21.524 ; 33.589,22.032 33.589,22.54 ; 33.589,22.032 34.097,22.032 ; 33.589,22.54 33.589,23.048 ; 33.589,22.54 34.097,22.54 ; 33.589,23.048 34.097,23.048 ; 33.589,23.048 33.589,23.554 ; 33.589,23.554 ccw(c34.605,24.445) 34.097,23.193 ; 33.589,25.588 33.589,26.096 ; 33.589,25.588 33.884,25.588 ; 33.589,26.096 33.589,26.604 ; 33.589,26.096 34.097,26.096 ; 33.589,26.604 33.589,27.112 ; 33.589,26.604 34.097,26.604 ; 33.589,27.112 33.589,27.62 ; 33.589,27.112 34.097,27.112 ; 33.589,27.62 33.589,28.128 ; 33.589,27.62 34.097,27.62 ; 33.589,28.128 33.589,28.636 ; 33.589,28.128 34.097,28.128 ; 33.589,28.636 33.589,29.144 ; 33.589,28.636 34.097,28.636 ; 33.589,29.144 33.589,29.652 ; 33.589,29.144 34.097,29.144 ; 33.589,29.652 33.589,30.16 ; 33.589,29.652 34.097,29.652 ; 33.589,30.16 33.589,30.668 ; 33.589,30.16 34.097,30.16 ; 33.589,30.668 33.589,31.176 ; 33.589,30.668 34.097,30.668 ; 33.589,31.176 33.589,31.684 ; 33.589,31.176 34.097,31.176 ; 33.589,31.684 33.589,32.192 ; 33.589,31.684 34.097,31.684 ; 33.589,32.192 33.589,32.7 ; 33.589,32.192 34.097,32.192 ; 33.589,32.7 33.589,33.208 ; 33.589,32.7 34.097,32.7 ; 33.589,33.208 33.589,33.716 ; 33.589,33.208 34.097,33.208 ; 33.589,33.716 33.589,34.224 ; 33.589,33.716 34.097,33.716 ; 33.589,34.224 33.589,34.732 ; 33.589,34.224 34.097,34.224 ; 33.589,34.732 33.589,35.24 ; 33.589,34.732 34.097,34.732 ; 33.589,35.24 34.097,35.24 ; 33.589,35.24 33.589,35.748 ; 33.589,35.748 34.097,35.748 ; 33.589,35.748 33.589,36.242 ; 33.589,36.242 33.709,36.122 ; 33.589,39.064 33.857,38.796 ; 33.589,39.064 33.589,39.304 ; 33.589,39.304 33.589,39.812 ; 33.589,39.304 34.097,39.304 ; 33.589,39.812 33.589,40.32 ; 33.589,39.812 34.097,39.812 ; 33.589,40.32 33.589,40.828 ; 33.589,40.32 34.097,40.32 ; 33.589,40.828 34.097,40.828 ; 33.589,40.828 33.589,41.336 ; 33.589,41.336 33.589,41.844 ; 33.589,41.336 34.097,41.336 ; 33.589,41.844 34.097,41.844 ; 33.589,41.844 33.589,42.352 ; 33.589,42.352 34.097,42.352 ; 33.589,42.352 33.589,42.86 ; 33.589,42.86 33.589,43.368 ; 33.589,42.86 34.097,42.86 ; 33.589,43.368 34.097,43.368 ; 33.589,43.368 33.589,43.876 ; 33.589,43.876 33.589,44.384 ; 33.589,43.876 34.097,43.876 ; 33.589,44.384 33.589,44.892 ; 33.589,44.384 34.097,44.384 ; 33.589,44.892 34.097,44.892 ; 33.589,44.892 33.589,45.4 ; 33.589,45.4 33.589,45.908 ; 33.589,45.4 34.097,45.4 ; 33.589,45.908 33.589,46.416 ; 33.589,45.908 34.097,45.908 ; 33.589,46.416 33.589,46.924 ; 33.589,46.416 34.097,46.416 ; 33.589,46.924 33.589,47.432 ; 33.589,46.924 34.097,46.924 ; 33.589,47.432 33.589,47.94 ; 33.589,47.432 34.097,47.432 ; 33.589,47.94 34.097,47.94 ; 33.589,47.94 33.589,48.448 ; 33.589,48.448 33.589,48.956 ; 33.589,48.448 34.097,48.448 ; 33.589,48.956 33.589,49.464 ; 33.589,48.956 34.097,48.956 ; 33.589,49.464 33.589,49.972 ; 33.589,49.464 34.097,49.464 ; 33.589,49.972 33.589,50.48 ; 33.589,49.972 34.097,49.972 ; 33.589,50.48 33.589,50.988 ; 33.589,50.48 34.097,50.48 ; 33.589,50.988 33.589,51.496 ; 33.589,50.988 34.097,50.988 ; 33.589,51.496 33.589,52.004 ; 33.589,51.496 34.097,51.496 ; 33.589,52.004 33.589,52.512 ; 33.589,52.004 34.097,52.004 ; 33.589,52.512 33.589,53.02 ; 33.589,52.512 34.097,52.512 ; 33.589,53.02 33.589,53.528 ; 33.589,53.02 34.097,53.02 ; 33.589,53.528 34.097,53.528 ; 33.589,53.528 33.589,54.036 ; 33.589,54.036 34.097,54.036 ; 33.589,54.036 33.589,54.073 ; 33.589,54.073 34.097,54.073 ; 33.709,36.122 ccw(c34.224,36.637) 34.097,35.92 ; 33.709,36.122 ccw(c34.224,36.637) 34.097,35.92 ; 33.857,38.796 34.097,38.796 ; 33.857,38.796 34.097,38.556 ; 33.884,25.588 cw(c34.605,24.445) 33.889,25.591 cw(c34.605,24.445) 34.097,25.697 ; 34.097,20.889 34.097,21.016 ; 34.097,20.889 34.605,20.889 ; 34.097,21.016 34.097,21.524 ; 34.097,21.016 34.605,21.016 ; 34.097,21.524 34.097,22.032 ; 34.097,21.524 34.605,21.524 ; 34.097,22.032 34.097,22.54 ; 34.097,22.032 34.605,22.032 ; 34.097,22.54 34.097,23.048 ; 34.097,22.54 34.605,22.54 ; 34.097,23.048 34.605,23.048 ; 34.097,23.048 34.097,23.193 ; 34.097,23.193 ccw(c34.605,24.445) 34.099,23.192 ccw(c34.605,24.445) 34.605,23.093 ; 34.097,25.697 cw(c34.605,24.445) 34.099,25.698 cw(c34.605,24.445) 34.605,25.797 ; 34.097,25.698 34.097,26.096 ; 34.097,26.096 34.097,26.604 ; 34.097,26.096 34.605,26.096 ; 34.097,26.604 34.097,27.112 ; 34.097,26.604 34.605,26.604 ; 34.097,27.112 34.097,27.62 ; 34.097,27.112 34.605,27.112 ; 34.097,27.62 34.097,28.128 ; 34.097,27.62 34.605,27.62 ; 34.097,28.128 34.097,28.636 ; 34.097,28.128 34.605,28.128 ; 34.097,28.636 34.097,29.144 ; 34.097,28.636 34.605,28.636 ; 34.097,29.144 34.097,29.652 ; 34.097,29.144 34.605,29.144 ; 34.097,29.652 34.097,30.16 ; 34.097,29.652 34.605,29.652 ; 34.097,30.16 34.097,30.668 ; 34.097,30.16 34.605,30.16 ; 34.097,30.668 34.097,31.176 ; 34.097,30.668 34.605,30.668 ; 34.097,31.176 34.097,31.684 ; 34.097,31.176 34.605,31.176 ; 34.097,31.684 34.097,32.192 ; 34.097,31.684 34.605,31.684 ; 34.097,32.192 34.097,32.7 ; 34.097,32.192 34.605,32.192 ; 34.097,32.7 34.097,33.208 ; 34.097,32.7 34.605,32.7 ; 34.097,33.208 34.097,33.716 ; 34.097,33.208 34.605,33.208 ; 34.097,33.716 34.097,34.224 ; 34.097,33.716 34.605,33.716 ; 34.097,34.224 34.097,34.732 ; 34.097,34.224 34.605,34.224 ; 34.097,34.732 34.097,35.24 ; 34.097,34.732 34.605,34.732 ; 34.097,35.24 34.605,35.24 ; 34.097,35.24 34.097,35.748 ; 34.097,35.748 34.605,35.748 ; 34.097,35.748 34.097,35.92 ; 34.097,35.92 ccw(c34.224,36.637) 34.224,35.908 ; 34.097,35.92 ccw(c34.224,36.637) 34.224,35.908 ; 34.097,38.556 34.097,38.796 ; 34.097,38.556 34.365,38.288 ; 34.097,38.796 34.097,39.304 ; 34.097,38.796 34.605,38.796 ; 34.097,39.304 34.097,39.812 ; 34.097,39.304 34.605,39.304 ; 34.097,39.812 34.097,40.32 ; 34.097,39.812 34.605,39.812 ; 34.097,40.32 34.097,40.828 ; 34.097,40.32 34.605,40.32 ; 34.097,40.828 34.097,41.336 ; 34.097,40.828 34.605,40.828 ; 34.097,41.336 34.097,41.844 ; 34.097,41.336 34.605,41.336 ; 34.097,41.844 34.097,42.352 ; 34.097,41.844 34.605,41.844 ; 34.097,42.352 34.097,42.86 ; 34.097,42.352 34.605,42.352 ; 34.097,42.86 34.097,43.368 ; 34.097,42.86 34.605,42.86 ; 34.097,43.368 34.097,43.876 ; 34.097,43.368 34.605,43.368 ; 34.097,43.876 34.097,44.384 ; 34.097,43.876 34.605,43.876 ; 34.097,44.384 34.097,44.892 ; 34.097,44.384 34.605,44.384 ; 34.097,44.892 34.097,45.4 ; 34.097,44.892 34.605,44.892 ; 34.097,45.4 34.097,45.908 ; 34.097,45.4 34.605,45.4 ; 34.097,45.908 34.097,46.416 ; 34.097,45.908 34.605,45.908 ; 34.097,46.416 34.097,46.924 ; 34.097,46.416 34.605,46.416 ; 34.097,46.924 34.097,47.432 ; 34.097,46.924 34.605,46.924 ; 34.097,47.432 34.097,47.94 ; 34.097,47.432 34.605,47.432 ; 34.097,47.94 34.097,48.448 ; 34.097,47.94 34.605,47.94 ; 34.097,48.448 34.097,48.956 ; 34.097,48.448 34.605,48.448 ; 34.097,48.956 34.097,49.464 ; 34.097,48.956 34.605,48.956 ; 34.097,49.464 34.097,49.972 ; 34.097,49.464 34.605,49.464 ; 34.097,49.972 34.097,50.48 ; 34.097,49.972 34.605,49.972 ; 34.097,50.48 34.097,50.988 ; 34.097,50.48 34.605,50.48 ; 34.097,50.988 34.097,51.496 ; 34.097,50.988 34.605,50.988 ; 34.097,51.496 34.097,52.004 ; 34.097,51.496 34.605,51.496 ; 34.097,52.004 34.097,52.512 ; 34.097,52.004 34.605,52.004 ; 34.097,52.512 34.097,53.02 ; 34.097,52.512 34.605,52.512 ; 34.097,53.02 34.097,53.528 ; 34.097,53.02 34.605,53.02 ; 34.097,53.528 34.097,54.036 ; 34.097,53.528 34.605,53.528 ; 34.097,54.036 34.097,54.073 ; 34.097,54.036 34.605,54.036 ; 34.097,54.073 34.605,54.073 ; 34.224,35.908 34.605,35.908 ; 34.365,38.288 34.605,38.288 ; 34.365,38.288 34.605,38.048 ; 34.605,20.889 34.605,21.016 ; 34.605,20.889 35.113,20.889 ; 34.605,21.016 34.605,21.524 ; 34.605,21.016 35.113,21.016 ; 34.605,21.524 34.605,22.032 ; 34.605,21.524 35.113,21.524 ; 34.605,22.032 34.605,22.54 ; 34.605,22.032 35.113,22.032 ; 34.605,22.54 34.605,23.048 ; 34.605,22.54 35.113,22.54 ; 34.605,23.048 35.113,23.048 ; 34.605,23.048 34.605,23.093 ; 34.605,23.093 ccw(c34.605,24.445) 35.111,23.192 ccw(c34.605,24.445) 35.113,23.192 ; 34.605,25.797 cw(c34.605,24.445) 35.111,25.698 cw(c34.605,24.445) 35.113,25.698 ; 34.605,25.797 34.605,26.096 ; 34.605,26.096 34.605,26.604 ; 34.605,26.096 35.113,26.096 ; 34.605,26.604 34.605,27.112 ; 34.605,26.604 35.113,26.604 ; 34.605,27.112 34.605,27.62 ; 34.605,27.112 35.113,27.112 ; 34.605,27.62 34.605,28.128 ; 34.605,27.62 35.113,27.62 ; 34.605,28.128 34.605,28.636 ; 34.605,28.128 35.113,28.128 ; 34.605,28.636 34.605,29.144 ; 34.605,28.636 35.113,28.636 ; 34.605,29.144 34.605,29.652 ; 34.605,29.144 35.113,29.144 ; 34.605,29.652 34.605,30.16 ; 34.605,29.652 35.113,29.652 ; 34.605,30.16 34.605,30.668 ; 34.605,30.16 35.077,30.16 ; 34.605,30.668 34.605,31.176 ; 34.605,30.668 34.981,30.668 ; 34.605,31.176 34.605,31.684 ; 34.605,31.176 35.077,31.176 ; 34.605,31.684 34.605,32.192 ; 34.605,31.684 35.113,31.684 ; 34.605,32.192 34.605,32.7 ; 34.605,32.192 35.113,32.192 ; 34.605,32.7 34.605,33.208 ; 34.605,32.7 35.113,32.7 ; 34.605,33.208 34.605,33.716 ; 34.605,33.208 35.113,33.208 ; 34.605,33.716 34.605,34.224 ; 34.605,33.716 35.085,33.716 ; 34.605,34.224 34.605,34.732 ; 34.605,34.224 35.085,34.224 ; 34.605,34.732 34.605,35.24 ; 34.605,34.732 35.113,34.732 ; 34.605,35.24 34.605,35.748 ; 34.605,35.24 35.113,35.24 ; 34.605,35.748 34.605,35.908 ; 34.605,35.748 35.113,35.748 ; 34.605,35.908 35.113,35.908 ; 34.605,38.048 34.605,38.288 ; 34.605,38.048 34.864,37.79 35.113,37.79 ; 34.605,38.288 34.605,38.796 ; 34.605,38.288 35.113,38.288 ; 34.605,38.796 34.605,39.304 ; 34.605,38.796 35.113,38.796 ; 34.605,39.304 34.605,39.812 ; 34.605,39.304 35.113,39.304 ; 34.605,39.812 34.605,40.32 ; 34.605,39.812 35.113,39.812 ; 34.605,40.32 34.605,40.828 ; 34.605,40.32 35.113,40.32 ; 34.605,40.828 34.605,41.336 ; 34.605,40.828 35.113,40.828 ; 34.605,41.336 34.605,41.844 ; 34.605,41.336 35.113,41.336 ; 34.605,41.844 34.605,42.352 ; 34.605,41.844 35.113,41.844 ; 34.605,42.352 34.605,42.86 ; 34.605,42.352 35.113,42.352 ; 34.605,42.86 34.605,43.368 ; 34.605,42.86 35.113,42.86 ; 34.605,43.368 34.605,43.876 ; 34.605,43.368 35.113,43.368 ; 34.605,43.876 34.605,44.384 ; 34.605,43.876 35.113,43.876 ; 34.605,44.384 34.605,44.892 ; 34.605,44.384 35.113,44.384 ; 34.605,44.892 34.605,45.4 ; 34.605,44.892 35.113,44.892 ; 34.605,45.4 34.605,45.908 ; 34.605,45.4 35.113,45.4 ; 34.605,45.908 34.605,46.416 ; 34.605,45.908 35.113,45.908 ; 34.605,46.416 34.605,46.924 ; 34.605,46.416 35.113,46.416 ; 34.605,46.924 34.605,47.432 ; 34.605,46.924 35.113,46.924 ; 34.605,47.432 34.605,47.94 ; 34.605,47.432 35.113,47.432 ; 34.605,47.94 34.605,48.448 ; 34.605,47.94 35.113,47.94 ; 34.605,48.448 34.605,48.956 ; 34.605,48.448 35.113,48.448 ; 34.605,48.956 34.605,49.464 ; 34.605,48.956 35.113,48.956 ; 34.605,49.464 34.605,49.972 ; 34.605,49.464 35.113,49.464 ; 34.605,49.972 34.605,50.48 ; 34.605,49.972 35.113,49.972 ; 34.605,50.48 34.605,50.988 ; 34.605,50.48 35.113,50.48 ; 34.605,50.988 34.605,51.496 ; 34.605,50.988 35.113,50.988 ; 34.605,51.496 34.605,52.004 ; 34.605,51.496 35.113,51.496 ; 34.605,52.004 34.605,52.512 ; 34.605,52.004 35.113,52.004 ; 34.605,52.512 34.605,53.02 ; 34.605,52.512 35.113,52.512 ; 34.605,53.02 34.605,53.528 ; 34.605,53.02 35.113,53.02 ; 34.605,53.528 34.605,54.036 ; 34.605,53.528 35.113,53.528 ; 34.605,54.036 34.605,54.073 ; 34.605,54.036 35.113,54.036 ; 34.605,54.073 35.113,54.073 ; 34.981,30.668 ccw(c36.383,30.668) 35.077,30.16 ; 34.981,30.668 cw(c36.383,30.668) 35.077,31.176 ; 35.085,33.716 cw(c36.463,33.97) 35.085,34.224 ; 35.085,34.224 cw(c36.463,33.97) 35.113,34.347 ; 35.113,20.889 35.113,21.016 ; 35.113,20.889 35.621,20.889 ; 35.113,21.016 35.113,21.524 ; 35.113,21.016 pad.@35.621,21.016 ; 35.113,21.524 35.113,22.032 ; 35.113,21.524 pad.@35.621,21.524 ; 35.113,22.032 35.113,22.54 ; 35.113,22.032 35.621,22.032 ; 35.113,22.54 35.113,23.048 ; 35.113,22.54 35.621,22.54 ; 35.113,23.048 35.621,23.048 ; 35.113,23.048 35.113,23.192 ; 35.113,23.192 ccw(c34.605,24.445) 35.621,23.554 ; 35.113,25.698 35.113,26.096 ; 35.113,26.096 35.113,26.604 ; 35.113,26.096 35.621,26.096 ; 35.113,26.604 35.113,27.112 ; 35.113,26.604 35.621,26.604 ; 35.113,27.112 35.113,27.62 ; 35.113,27.112 35.621,27.112 ; 35.113,27.62 35.113,28.128 ; 35.113,27.62 35.621,27.62 ; 35.113,28.128 35.113,28.636 ; 35.113,28.128 35.621,28.128 ; 35.113,28.636 35.113,29.144 ; 35.113,28.636 35.621,28.636 ; 35.113,29.144 35.113,29.652 ; 35.113,29.144 35.621,29.144 ; 35.113,29.652 35.417,29.652 ; 35.113,29.652 35.113,30.075 ccw(c36.383,30.668) 35.409,29.66 ccw(c36.383,30.668) 35.417,29.652 ; 35.113,31.684 35.113,32.192 ; 35.113,31.684 35.113,31.261 cw(c36.383,30.668) 35.409,31.676 cw(c36.383,30.668) 35.417,31.684 ; 35.113,31.684 35.417,31.684 ; 35.113,32.192 35.113,32.7 ; 35.113,32.192 35.621,32.192 ; 35.113,32.7 35.113,33.208 ; 35.113,32.7 35.621,32.7 ; 35.113,33.208 35.287,33.208 ; 35.113,34.347 cw(c36.463,33.97) 35.116,34.356 cw(c36.463,33.97) 35.287,34.732 ; 35.113,34.347 35.113,34.732 ; 35.113,34.732 35.113,35.24 ; 35.113,34.732 35.287,34.732 ; 35.113,35.24 35.113,35.748 ; 35.113,35.24 35.621,35.24 ; 35.113,35.748 35.113,35.908 ; 35.113,35.748 35.621,35.748 ; 35.113,35.908 35.621,35.908 ; 35.113,37.79 35.113,38.288 ; 35.113,37.79 35.621,37.79 ; 35.113,38.288 35.113,38.796 ; 35.113,38.288 35.621,38.288 ; 35.113,38.796 35.113,39.304 ; 35.113,38.796 35.621,38.796 ; 35.113,39.304 35.113,39.812 ; 35.113,39.304 35.621,39.304 ; 35.113,39.812 35.113,40.32 ; 35.113,39.812 35.621,39.812 ; 35.113,40.32 35.113,40.828 ; 35.113,40.32 35.621,40.32 ; 35.113,40.828 35.113,41.336 ; 35.113,40.828 35.621,40.828 ; 35.113,41.336 35.113,41.844 ; 35.113,41.336 35.621,41.336 ; 35.113,41.844 35.113,42.352 ; 35.113,41.844 35.621,41.844 ; 35.113,42.352 35.113,42.86 ; 35.113,42.352 35.621,42.352 ; 35.113,42.86 35.113,43.368 ; 35.113,42.86 35.621,42.86 ; 35.113,43.368 35.113,43.876 ; 35.113,43.368 35.621,43.368 ; 35.113,43.876 35.113,44.384 ; 35.113,43.876 35.621,43.876 ; 35.113,44.384 35.113,44.892 ; 35.113,44.384 35.621,44.384 ; 35.113,44.892 35.113,45.4 ; 35.113,44.892 35.621,44.892 ; 35.113,45.4 35.113,45.908 ; 35.113,45.4 35.621,45.4 ; 35.113,45.908 35.113,46.416 ; 35.113,45.908 35.621,45.908 ; 35.113,46.416 35.113,46.924 ; 35.113,46.416 35.621,46.416 ; 35.113,46.924 35.113,47.432 ; 35.113,46.924 35.621,46.924 ; 35.113,47.432 35.113,47.94 ; 35.113,47.432 35.621,47.432 ; 35.113,47.94 35.113,48.448 ; 35.113,47.94 35.621,47.94 ; 35.113,48.448 35.113,48.956 ; 35.113,48.448 35.621,48.448 ; 35.113,48.956 35.113,49.464 ; 35.113,48.956 35.621,48.956 ; 35.113,49.464 35.113,49.972 ; 35.113,49.464 35.621,49.464 ; 35.113,49.972 35.113,50.48 ; 35.113,49.972 35.621,49.972 ; 35.113,50.48 35.113,50.988 ; 35.113,50.48 35.621,50.48 ; 35.113,50.988 35.113,51.496 ; 35.113,50.988 35.621,50.988 ; 35.113,51.496 35.113,52.004 ; 35.113,51.496 35.621,51.496 ; 35.113,52.004 35.113,52.512 ; 35.113,52.004 35.621,52.004 ; 35.113,52.512 35.113,53.02 ; 35.113,52.512 35.621,52.512 ; 35.113,53.02 35.113,53.528 ; 35.113,53.02 35.621,53.02 ; 35.113,53.528 35.113,54.036 ; 35.113,53.528 35.621,53.528 ; 35.113,54.036 35.113,54.073 ; 35.113,54.036 35.621,54.036 ; 35.113,54.073 35.621,54.073 ; 35.287,33.208 ccw(c36.463,33.97) 35.288,33.207 ccw(c36.463,33.97) 35.62,32.851 ccw(c36.463,33.97) 35.621,32.849 ; 35.287,34.732 cw(c36.463,33.97) 35.62,35.089 cw(c36.463,33.97) 35.621,35.091 ; 35.417,29.652 ccw(c36.383,30.668) 35.62,29.493 ccw(c36.383,30.668) 35.621,29.492 ; 35.621,20.889 pad.@35.621,21.016 ; 35.621,20.889 36.129,20.889 ; pad.@35.621,21.016 pad.@35.621,21.524 ; pad.@35.621,21.016 36.129,21.016 ; pad.@35.621,21.524 35.621,22.032 ; pad.@35.621,21.524 36.129,21.524 ; 35.621,22.032 35.621,22.54 ; 35.621,22.032 36.129,22.032 ; 35.621,22.54 35.621,23.048 ; 35.621,22.54 36.129,22.54 ; 35.621,23.048 36.129,23.048 ; 35.621,23.048 35.621,23.554 ; 35.621,23.554 ccw(c34.605,24.445) 35.623,23.556 ; 35.621,25.336 cw(c34.605,24.445) 35.625,25.332 cw(c34.605,24.445) 35.798,25.08 ; 35.621,25.336 35.621,25.588 ; 35.621,25.588 35.621,26.096 ; 35.621,25.588 36.129,25.588 ; 35.621,26.096 35.621,26.604 ; 35.621,26.096 36.129,26.096 ; 35.621,26.604 35.621,27.112 ; 35.621,26.604 36.129,26.604 ; 35.621,27.112 35.621,27.62 ; 35.621,27.112 36.129,27.112 ; 35.621,27.62 35.621,28.128 ; 35.621,27.62 36.129,27.62 ; 35.621,28.128 35.621,28.636 ; 35.621,28.128 36.129,28.128 ; 35.621,28.636 35.621,29.144 ; 35.621,28.636 36.129,28.636 ; 35.621,29.144 36.129,29.144 ; 35.621,29.144 35.621,29.492 ; 35.621,32.192 35.621,32.7 ; 35.621,32.192 36.129,32.192 ; 35.621,32.7 35.621,32.849 ; 35.621,32.7 35.87,32.7 cw(c36.463,33.97) 35.621,32.849 ; 35.621,35.091 cw(c36.463,33.97) 35.87,35.24 ; 35.621,35.091 35.621,35.24 ; 35.621,35.24 35.621,35.748 ; 35.621,35.24 35.87,35.24 ; 35.621,35.748 35.621,35.908 ; 35.621,35.748 36.129,35.748 ; 35.621,35.908 36.129,35.908 ; 35.621,37.79 35.621,38.288 ; 35.621,37.79 36.129,37.79 ; 35.621,38.288 35.621,38.796 ; 35.621,38.288 36.129,38.288 ; 35.621,38.796 35.621,39.304 ; 35.621,38.796 36.129,38.796 ; 35.621,39.304 35.621,39.812 ; 35.621,39.304 36.129,39.304 ; 35.621,39.812 35.621,40.32 ; 35.621,39.812 36.129,39.812 ; 35.621,40.32 35.621,40.828 ; 35.621,40.32 36.129,40.32 ; 35.621,40.828 35.621,41.336 ; 35.621,40.828 36.129,40.828 ; 35.621,41.336 35.621,41.844 ; 35.621,41.336 36.129,41.336 ; 35.621,41.844 35.621,42.352 ; 35.621,41.844 36.129,41.844 ; 35.621,42.352 35.621,42.86 ; 35.621,42.352 36.129,42.352 ; 35.621,42.86 35.621,43.368 ; 35.621,42.86 36.129,42.86 ; 35.621,43.368 35.621,43.876 ; 35.621,43.368 36.129,43.368 ; 35.621,43.876 35.621,44.384 ; 35.621,43.876 36.129,43.876 ; 35.621,44.384 35.621,44.892 ; 35.621,44.384 36.129,44.384 ; 35.621,44.892 35.621,45.4 ; 35.621,44.892 36.129,44.892 ; 35.621,45.4 35.621,45.908 ; 35.621,45.4 36.129,45.4 ; 35.621,45.908 35.621,46.416 ; 35.621,45.908 36.129,45.908 ; 35.621,46.416 35.621,46.924 ; 35.621,46.416 36.129,46.416 ; 35.621,46.924 35.621,47.432 ; 35.621,46.924 36.129,46.924 ; 35.621,47.432 35.621,47.94 ; 35.621,47.432 36.129,47.432 ; 35.621,47.94 35.621,48.448 ; 35.621,47.94 36.129,47.94 ; 35.621,48.448 35.621,48.956 ; 35.621,48.448 36.129,48.448 ; 35.621,48.956 35.621,49.464 ; 35.621,48.956 36.129,48.956 ; 35.621,49.464 35.621,49.972 ; 35.621,49.464 36.129,49.464 ; 35.621,49.972 35.621,50.48 ; 35.621,49.972 36.129,49.972 ; 35.621,50.48 35.621,50.988 ; 35.621,50.48 36.129,50.48 ; 35.621,50.988 35.621,51.496 ; 35.621,50.988 36.129,50.988 ; 35.621,51.496 35.621,52.004 ; 35.621,51.496 36.129,51.496 ; 35.621,52.004 35.621,52.512 ; 35.621,52.004 36.129,52.004 ; 35.621,52.512 35.621,53.02 ; 35.621,52.512 36.129,52.512 ; 35.621,53.02 35.621,53.528 ; 35.621,53.02 36.129,53.02 ; 35.621,53.528 35.621,54.036 ; 35.621,53.528 36.129,53.528 ; 35.621,54.036 35.621,54.073 ; 35.621,54.036 36.129,54.036 ; 35.621,54.073 36.129,54.073 ; 35.623,23.556 ccw(c34.605,24.445) 35.625,23.558 ccw(c34.605,24.445) 35.875,23.982 ccw(c37.145,24.445) 36.125,23.558 ccw(c37.145,24.445) 36.127,23.556 ; 35.623,23.556 36.127,23.556 ; 35.798,25.08 cw(c34.605,24.445) 35.875,24.908 cw(c37.145,24.445) 35.952,25.08 ; 35.798,25.08 35.952,25.08 ; 35.87,35.24 cw(c36.463,33.97) 36.124,35.33 cw(c36.463,33.97) 36.129,35.331 ; 36.127,23.556 ccw(c37.145,24.445) 36.129,23.554 ; 36.129,20.889 36.129,21.016 ; 36.129,20.889 36.637,20.889 ; 36.129,21.016 36.637,21.016 ; 36.129,21.016 36.129,21.524 ; 36.129,21.524 36.129,22.032 ; 36.129,21.524 36.637,21.524 ; 36.129,22.032 36.129,22.54 ; 36.129,22.032 36.637,22.032 ; 36.129,22.54 36.129,23.048 ; 36.129,22.54 36.637,22.54 ; 36.129,23.048 36.637,23.048 ; 36.129,23.048 36.129,23.554 ; 36.129,23.554 ccw(c37.145,24.445) 36.637,23.193 ; 36.129,25.588 36.129,26.096 ; 36.129,25.588 36.424,25.588 ; 36.129,26.096 36.129,26.604 ; 36.129,26.096 36.637,26.096 ; 36.129,26.604 36.129,27.112 ; 36.129,26.604 36.637,26.604 ; 36.129,27.112 36.129,27.62 ; 36.129,27.112 36.637,27.112 ; 36.129,27.62 36.129,28.128 ; 36.129,27.62 36.637,27.62 ; 36.129,28.128 36.129,28.636 ; 36.129,28.128 36.637,28.128 ; 36.129,28.636 36.129,29.144 ; 36.129,28.636 36.637,28.636 ; 36.129,29.144 36.637,29.144 ; 36.129,32.046 cw(c36.383,30.668) 36.626,32.048 cw(c36.383,30.668) 36.637,32.046 ; 36.129,32.046 36.129,32.192 ; 36.129,32.192 36.637,32.192 ; 36.129,32.192 36.129,32.609 ; 36.129,32.609 ccw(c36.463,33.97) 36.634,32.579 ccw(c36.463,33.97) 36.637,32.579 ; 36.129,35.331 cw(c36.463,33.97) 36.634,35.361 cw(c36.463,33.97) 36.637,35.361 ; 36.129,35.331 36.129,35.748 ; 36.129,35.748 36.129,35.908 ; 36.129,35.748 36.637,35.748 ; 36.129,35.908 36.637,35.908 ; 36.129,37.79 36.129,38.288 ; 36.129,37.79 36.637,37.79 ; 36.129,38.288 36.129,38.796 ; 36.129,38.288 36.637,38.288 ; 36.129,38.796 36.129,39.304 ; 36.129,38.796 36.637,38.796 ; 36.129,39.304 36.129,39.812 ; 36.129,39.304 36.637,39.304 ; 36.129,39.812 36.129,40.32 ; 36.129,39.812 36.637,39.812 ; 36.129,40.32 36.129,40.828 ; 36.129,40.32 36.637,40.32 ; 36.129,40.828 36.129,41.336 ; 36.129,40.828 36.637,40.828 ; 36.129,41.336 36.129,41.844 ; 36.129,41.336 36.637,41.336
